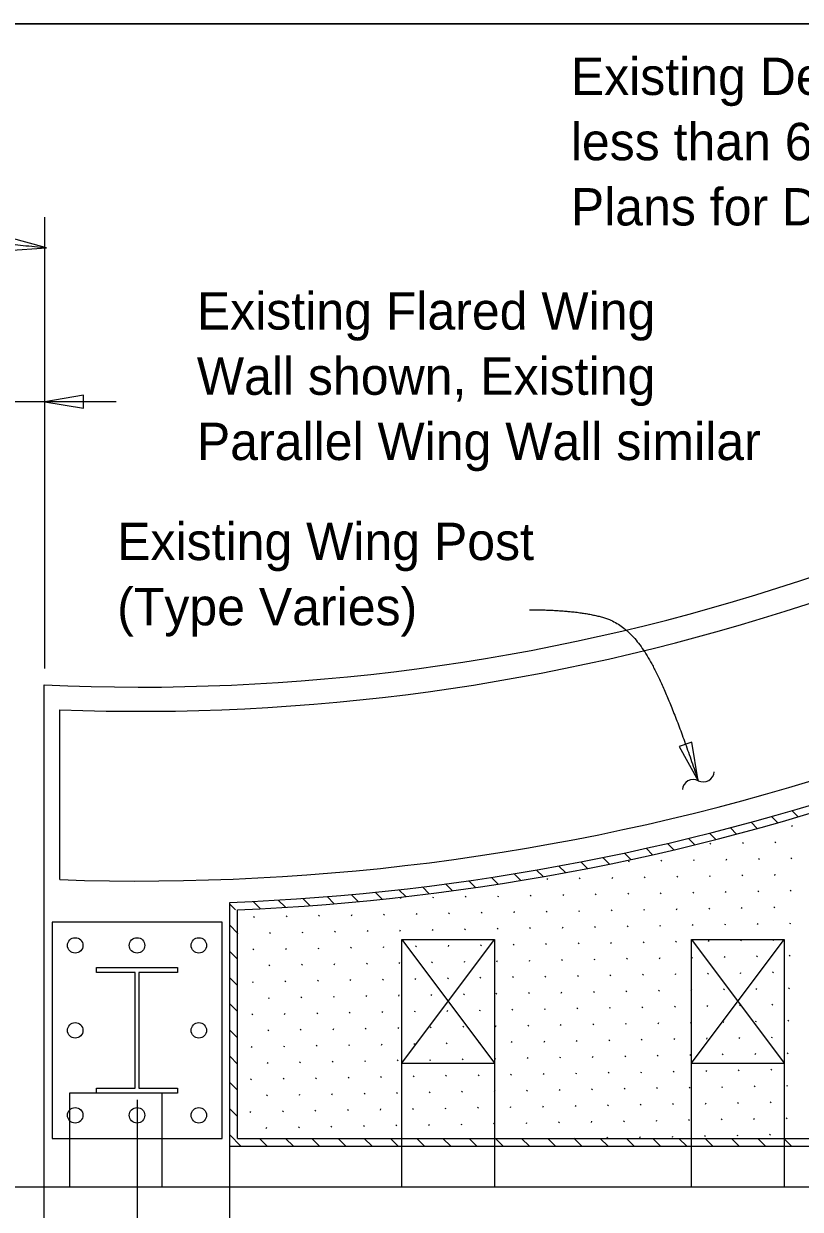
# Model space of a CAD drawing. Extents: x 0 to 41.1, y 0 to 25.9.
# Drawn here: x 27.57 to 31.76, y 19.55 to 25.95 of the extents above; entities that cross this region are included whole.
import ezdxf

# ---------------------------------------------------------------- set-up
doc = ezdxf.new("R2010")
doc.units = 0
for name, color, linetype in [('Dimension', 7, 'Continuous'), ('ExistSuperStruct', 7, 'Continuous'), ('Miscellaneous', 7, 'Continuous'), ('Miscellaneous1', 7, 'Continuous'), ('SteelMisc_h', 7, 'Continuous')]:
    doc.layers.add(name, color=color, linetype=linetype)

msp = doc.modelspace()

# ---------------------------------------------------------------- linework, layer by layer
at = {"layer": 'Dimension'}
for p, q in [((27.6878, 22.467), (27.6878, 24.9023)), ((28.0733, 23.9065), (23.9735, 23.9065)), ((28.1854, 20.1392), (28.1854, 17.6446))]:
    msp.add_line(p, q, dxfattribs=at)
for points in [[(0, 0), (41.0506, 0), (41.0506, 25.9461), (0, 25.9461)], [(27.6973, 24.7374), (27.4936, 24.7932), (27.4865, 24.723)], [(27.6879, 23.9065), (27.8961, 23.8712), (27.8961, 23.9418)], [(31.2113, 21.8616), (31.1762, 22.0699), (31.1095, 22.0467)]]:
    msp.add_lwpolyline(points, close=True, dxfattribs=at)
for centre, start, end in [((31.2387, 21.9152), 243.37602, 355.10324), ((31.1853, 21.8086), 63.37602, 175.10324)]:
    msp.add_arc(centre, 0.0596, start, end, dxfattribs=at)
for points in [[(26.5757, 24.9815), (26.7604, 24.9749), (26.9979, 24.8759), (27.0309, 24.8165), (27.3014, 24.7769), (27.6972, 24.7373)], [(30.3021, 22.7841), (30.5512, 22.7841), (30.8439, 22.7031), (31.0618, 22.3104), (31.2113, 21.8616)]]:
    msp.add_open_spline(points, degree=2, dxfattribs=at)
at = {"layer": 'ExistSuperStruct'}
for p, q in [((27.6854, 17.9125), (27.6854, 22.3785)), ((27.7687, 21.328), (27.7687, 22.244)), ((28.6854, 17.9125), (28.6854, 21.205)), ((28.7271, 19.9322), (28.7271, 21.165)), ((28.7271, 19.9322), (35.7954, 19.9322)), ((28.6854, 19.8905), (35.7954, 19.8905))]:
    msp.add_line(p, q, dxfattribs=at)
for radius, start, end in [(11.3394, 267.40102, 307.93264), (11.4702, 267.84731, 307.49092), (12.3856, 268.00648, 307.27295), (12.5106, 272.22541, 307.24718), (12.5523, 272.40859, 307.2387)]:
    msp.add_arc((28.1995, 33.7062), radius, start, end, dxfattribs=at)
at = {"layer": 'Miscellaneous'}
for p, q in [((31.7168, 21.7002), (31.7504, 21.6666)), ((31.4964, 21.6378), (31.5302, 21.6039)), ((31.607, 21.6685), (31.6403, 21.6352)), ((31.7163, 21.6156), (31.7195, 21.6212)), ((31.2725, 21.5788), (31.3067, 21.5446)), ((31.3848, 21.6078), (31.4185, 21.5742)), ((30.9299, 21.4971), (30.9643, 21.4627)), ((31.045, 21.5234), (31.0796, 21.4888)), ((31.1592, 21.5507), (31.1932, 21.5166)), ((31.2764, 21.5199), (31.2797, 21.5255)), ((31.4517, 21.5231), (31.455, 21.5287)), ((31.627, 21.5264), (31.6303, 21.532)), ((30.6968, 21.4473), (30.7317, 21.4125)), ((30.8138, 21.4717), (30.8488, 21.4368)), ((30.8365, 21.4241), (30.8398, 21.4297)), ((31.0118, 21.4274), (31.0151, 21.433)), ((31.1871, 21.4306), (31.1904, 21.4362)), ((31.3624, 21.4339), (31.3657, 21.4395)), ((31.5377, 21.4371), (31.541, 21.4427)), ((31.7131, 21.4403), (31.7163, 21.4459)), ((30.3399, 21.38), (30.3756, 21.3443)), ((30.4599, 21.4014), (30.4952, 21.3661)), ((30.5789, 21.4239), (30.6142, 21.3886)), ((29.8494, 21.3048), (29.886, 21.2682)), ((29.9737, 21.322), (30.0102, 21.2855)), ((30.0968, 21.3402), (30.133, 21.3041)), ((30.2189, 21.3596), (30.2548, 21.3237)), ((30.3967, 21.3284), (30.3999, 21.334)), ((30.572, 21.3316), (30.5752, 21.3372)), ((30.7473, 21.3349), (30.7505, 21.3405)), ((30.9226, 21.3381), (30.9258, 21.3437)), ((31.0979, 21.3413), (31.1011, 21.3469)), ((31.2732, 21.3446), (31.2764, 21.3502)), ((31.4485, 21.3478), (31.4517, 21.3534)), ((31.6238, 21.3511), (31.627, 21.3567)), ((29.3408, 21.2477), (29.3786, 21.2099)), ((29.4698, 21.2602), (29.5077, 21.2223)), ((29.5975, 21.2739), (29.6347, 21.2367)), ((29.724, 21.2888), (29.7612, 21.2516)), ((29.9568, 21.2326), (29.96, 21.2382)), ((30.1321, 21.2359), (30.1353, 21.2415)), ((30.3074, 21.2391), (30.3106, 21.2447)), ((30.4827, 21.2424), (30.4859, 21.2479)), ((30.658, 21.2456), (30.6612, 21.2512)), ((30.8333, 21.2488), (30.8365, 21.2544)), ((31.0086, 21.2521), (31.0118, 21.2577)), ((31.1839, 21.2553), (31.1871, 21.2609)), ((31.3592, 21.2586), (31.3624, 21.2642)), ((31.5345, 21.2618), (31.5377, 21.2674)), ((31.7098, 21.265), (31.7131, 21.2706)), ((28.6854, 21.1961), (28.7164, 21.165)), ((28.8123, 21.2106), (28.8518, 21.171)), ((28.9464, 21.2179), (28.9853, 21.1789)), ((29.0792, 21.2265), (29.1178, 21.1879)), ((29.2106, 21.2365), (29.249, 21.1981)), ((29.6062, 21.2261), (29.6094, 21.2317)), ((29.7815, 21.2294), (29.7847, 21.235)), ((31.2699, 21.1693), (31.2732, 21.1749)), ((31.4452, 21.1725), (31.4485, 21.1781)), ((31.6205, 21.1758), (31.6238, 21.1814)), ((28.8157, 21.1239), (28.8189, 21.1295)), ((28.991, 21.1272), (28.9942, 21.1327)), ((29.1663, 21.1304), (29.1695, 21.136)), ((29.3416, 21.1336), (29.3448, 21.1392)), ((29.5169, 21.1369), (29.5201, 21.1425)), ((29.6922, 21.1401), (29.6954, 21.1457)), ((29.8675, 21.1434), (29.8707, 21.149)), ((30.0428, 21.1466), (30.046, 21.1522)), ((30.2181, 21.1498), (30.2213, 21.1554)), ((30.3934, 21.1531), (30.3967, 21.1587)), ((30.5687, 21.1563), (30.572, 21.1619)), ((30.744, 21.1596), (30.7473, 21.1652)), ((30.9193, 21.1628), (30.9226, 21.1684)), ((31.0946, 21.166), (31.0979, 21.1716)), ((28.6854, 21.0818), (28.7271, 21.0401)), ((29.077, 21.0411), (29.0803, 21.0467)), ((29.2523, 21.0444), (29.2556, 21.05)), ((29.4276, 21.0476), (29.4309, 21.0532)), ((29.6029, 21.0508), (29.6062, 21.0564)), ((29.7782, 21.0541), (29.7815, 21.0597)), ((29.9535, 21.0573), (29.9568, 21.0629)), ((30.1288, 21.0606), (30.1321, 21.0662)), ((30.3041, 21.0638), (30.3074, 21.0694)), ((30.4794, 21.067), (30.4827, 21.0726)), ((30.6547, 21.0703), (30.658, 21.0759)), ((30.8301, 21.0735), (30.8333, 21.0791)), ((31.0054, 21.0768), (31.0086, 21.0824)), ((31.1807, 21.08), (31.1839, 21.0856)), ((31.356, 21.0833), (31.3592, 21.0889)), ((31.5313, 21.0865), (31.5345, 21.0921)), ((31.7066, 21.0897), (31.7098, 21.0953)), ((28.7271, 21.0358), (28.7296, 21.0402)), ((28.9017, 21.0379), (28.905, 21.0435)), ((29.6124, 19.6709), (29.6124, 21.0042)), ((29.6124, 21.0042), (30.1124, 21.0042)), ((29.6124, 21.0042), (30.1124, 20.3376)), ((29.6124, 20.3376), (30.1124, 21.0042)), ((30.1124, 21.0042), (30.1124, 19.6709)), ((30.3902, 20.9778), (30.3934, 20.9834)), ((30.5655, 20.981), (30.5687, 20.9866)), ((30.7408, 20.9843), (30.744, 20.9899)), ((30.9161, 20.9875), (30.9193, 20.9931)), ((31.0914, 20.9907), (31.0946, 20.9963)), ((31.1749, 19.6709), (31.1749, 21.0042)), ((31.1749, 21.0042), (31.6749, 21.0042)), ((31.1749, 21.0042), (31.6749, 20.3376)), ((31.1749, 20.3376), (31.6749, 21.0042)), ((31.2667, 20.994), (31.2699, 20.9996)), ((31.442, 20.9972), (31.4452, 21.0028)), ((31.6173, 21.0005), (31.6205, 21.0061)), ((31.6749, 21.0042), (31.6749, 19.6709)), ((28.6854, 20.9404), (28.7271, 20.8987)), ((28.8124, 20.9486), (28.8157, 20.9542)), ((28.9877, 20.9518), (28.991, 20.9574)), ((29.163, 20.9551), (29.1663, 20.9607)), ((29.3384, 20.9583), (29.3416, 20.9639)), ((29.5137, 20.9616), (29.5169, 20.9672)), ((29.689, 20.9648), (29.6922, 20.9704)), ((29.8643, 20.9681), (29.8675, 20.9737)), ((30.0396, 20.9713), (30.0428, 20.9769)), ((30.2149, 20.9745), (30.2181, 20.9801)), ((31.7033, 20.9144), (31.7066, 20.92)), ((28.8985, 20.8626), (28.9017, 20.8682)), ((29.0738, 20.8658), (29.077, 20.8714)), ((29.2491, 20.8691), (29.2523, 20.8747)), ((29.4244, 20.8723), (29.4276, 20.8779)), ((29.5997, 20.8755), (29.6029, 20.8811)), ((29.775, 20.8788), (29.7782, 20.8844)), ((29.9503, 20.882), (29.9535, 20.8876)), ((30.1256, 20.8853), (30.1288, 20.8909)), ((30.3009, 20.8885), (30.3041, 20.8941)), ((30.4762, 20.8917), (30.4794, 20.8973)), ((30.6515, 20.895), (30.6547, 20.9006)), ((30.8268, 20.8982), (30.8301, 20.9038)), ((31.0021, 20.9015), (31.0054, 20.9071)), ((31.1774, 20.9047), (31.1807, 20.9103)), ((31.3527, 20.9079), (31.356, 20.9135)), ((31.528, 20.9112), (31.5313, 20.9168)), ((28.6854, 20.799), (28.7271, 20.7573)), ((29.5104, 20.7863), (29.5137, 20.7919)), ((29.6857, 20.7895), (29.689, 20.7951)), ((29.861, 20.7927), (29.8643, 20.7983)), ((30.0363, 20.796), (30.0396, 20.8016)), ((30.2116, 20.7992), (30.2149, 20.8048)), ((30.3869, 20.8025), (30.3902, 20.8081)), ((30.5622, 20.8057), (30.5655, 20.8113)), ((30.7375, 20.809), (30.7408, 20.8146)), ((30.9128, 20.8122), (30.9161, 20.8178)), ((31.0881, 20.8154), (31.0914, 20.821)), ((31.2634, 20.8187), (31.2667, 20.8243)), ((31.4388, 20.8219), (31.442, 20.8275)), ((31.6141, 20.8252), (31.6173, 20.8308)), ((28.8092, 20.7733), (28.8124, 20.7789)), ((28.9845, 20.7765), (28.9877, 20.7821)), ((29.1598, 20.7798), (29.163, 20.7854)), ((29.3351, 20.783), (29.3384, 20.7886)), ((30.8236, 20.7229), (30.8268, 20.7285)), ((30.9989, 20.7262), (31.0021, 20.7318)), ((31.1742, 20.7294), (31.1774, 20.735)), ((31.3495, 20.7326), (31.3527, 20.7382)), ((31.5248, 20.7359), (31.528, 20.7415)), ((31.7001, 20.7391), (31.7033, 20.7447)), ((28.8952, 20.6873), (28.8985, 20.6929)), ((29.0705, 20.6905), (29.0738, 20.6961)), ((29.2458, 20.6938), (29.2491, 20.6994)), ((29.4211, 20.697), (29.4244, 20.7026)), ((29.5964, 20.7002), (29.5997, 20.7058)), ((29.7717, 20.7035), (29.775, 20.7091)), ((29.9471, 20.7067), (29.9503, 20.7123)), ((30.1224, 20.71), (30.1256, 20.7156)), ((30.2977, 20.7132), (30.3009, 20.7188)), ((30.473, 20.7164), (30.4762, 20.722)), ((30.6483, 20.7197), (30.6515, 20.7253)), ((28.6854, 20.6575), (28.7271, 20.6158)), ((28.806, 20.598), (28.8092, 20.6036)), ((28.9813, 20.6012), (28.9845, 20.6068)), ((29.1566, 20.6045), (29.1598, 20.6101)), ((29.3319, 20.6077), (29.3351, 20.6133)), ((29.5072, 20.611), (29.5104, 20.6166)), ((29.6825, 20.6142), (29.6857, 20.6198)), ((29.8578, 20.6174), (29.861, 20.623)), ((30.0331, 20.6207), (30.0363, 20.6263)), ((30.2084, 20.6239), (30.2116, 20.6295)), ((30.3837, 20.6272), (30.3869, 20.6328)), ((30.559, 20.6304), (30.5622, 20.636)), ((30.7343, 20.6337), (30.7375, 20.6392)), ((30.9096, 20.6369), (30.9128, 20.6425)), ((31.0849, 20.6401), (31.0881, 20.6457)), ((31.2602, 20.6434), (31.2634, 20.649)), ((31.4355, 20.6466), (31.4388, 20.6522)), ((31.6108, 20.6499), (31.6141, 20.6555)), ((29.7685, 20.5282), (29.7717, 20.5338)), ((29.9438, 20.5314), (29.9471, 20.537)), ((30.1191, 20.5347), (30.1224, 20.5403)), ((30.2944, 20.5379), (30.2977, 20.5435)), ((30.4697, 20.5411), (30.473, 20.5467)), ((30.645, 20.5444), (30.6483, 20.55)), ((30.8203, 20.5476), (30.8236, 20.5532)), ((30.9956, 20.5509), (30.9989, 20.5565)), ((31.1709, 20.5541), (31.1742, 20.5597)), ((31.3462, 20.5573), (31.3495, 20.5629)), ((31.5215, 20.5606), (31.5248, 20.5662)), ((31.6968, 20.5638), (31.7001, 20.5694)), ((28.6854, 20.5161), (28.7271, 20.4744)), ((28.892, 20.512), (28.8952, 20.5176)), ((29.0673, 20.5152), (29.0705, 20.5208)), ((29.2426, 20.5185), (29.2458, 20.524)), ((29.4179, 20.5217), (29.4211, 20.5273)), ((29.5932, 20.5249), (29.5964, 20.5305)), ((31.0817, 20.4648), (31.0849, 20.4704)), ((31.257, 20.4681), (31.2602, 20.4737)), ((31.4323, 20.4713), (31.4355, 20.4769)), ((31.6076, 20.4746), (31.6108, 20.4801)), ((28.8027, 20.4227), (28.806, 20.4283)), ((28.978, 20.4259), (28.9813, 20.4315)), ((29.1533, 20.4292), (29.1566, 20.4348)), ((29.3286, 20.4324), (29.3319, 20.438)), ((29.5039, 20.4357), (29.5072, 20.4413)), ((29.6792, 20.4389), (29.6825, 20.4445)), ((29.8545, 20.4421), (29.8578, 20.4477)), ((30.0298, 20.4454), (30.0331, 20.451)), ((30.2051, 20.4486), (30.2084, 20.4542)), ((30.3804, 20.4519), (30.3837, 20.4575)), ((30.5558, 20.4551), (30.559, 20.4607)), ((30.7311, 20.4583), (30.7343, 20.4639)), ((30.9064, 20.4616), (30.9096, 20.4672)), ((28.6854, 20.3747), (28.7271, 20.333)), ((28.8887, 20.3367), (28.892, 20.3423)), ((29.0641, 20.3399), (29.0673, 20.3455)), ((29.2394, 20.3431), (29.2426, 20.3487)), ((29.4147, 20.3464), (29.4179, 20.352)), ((29.59, 20.3496), (29.5932, 20.3552)), ((29.7653, 20.3529), (29.7685, 20.3585)), ((29.9406, 20.3561), (29.9438, 20.3617)), ((30.1159, 20.3594), (30.1191, 20.3649)), ((30.2912, 20.3626), (30.2944, 20.3682)), ((30.4665, 20.3658), (30.4697, 20.3714)), ((30.6418, 20.3691), (30.645, 20.3747)), ((30.8171, 20.3723), (30.8203, 20.3779)), ((30.9924, 20.3756), (30.9956, 20.3812)), ((31.1677, 20.3788), (31.1709, 20.3844)), ((31.343, 20.382), (31.3462, 20.3876)), ((31.5183, 20.3853), (31.5215, 20.3909)), ((31.6936, 20.3885), (31.6968, 20.3941)), ((29.6124, 20.3376), (30.1124, 20.3376)), ((30.2019, 20.2733), (30.2051, 20.2789)), ((30.3772, 20.2766), (30.3804, 20.2822)), ((30.5525, 20.2798), (30.5558, 20.2854)), ((30.7278, 20.283), (30.7311, 20.2886)), ((30.9031, 20.2863), (30.9064, 20.2919)), ((31.0784, 20.2895), (31.0817, 20.2951)), ((31.1749, 20.3376), (31.6749, 20.3376)), ((31.2537, 20.2928), (31.257, 20.2984)), ((31.429, 20.296), (31.4323, 20.3016)), ((31.6043, 20.2992), (31.6076, 20.3048)), ((28.6854, 20.2333), (28.7271, 20.1916)), ((28.7995, 20.2474), (28.8027, 20.253)), ((28.9748, 20.2506), (28.978, 20.2562)), ((29.1501, 20.2539), (29.1533, 20.2595)), ((29.3254, 20.2571), (29.3286, 20.2627)), ((29.5007, 20.2604), (29.5039, 20.266)), ((29.676, 20.2636), (29.6792, 20.2692)), ((29.8513, 20.2668), (29.8545, 20.2724)), ((30.0266, 20.2701), (30.0298, 20.2757)), ((31.5151, 20.21), (31.5183, 20.2156)), ((31.6904, 20.2132), (31.6936, 20.2188)), ((28.3208, 20.1764), (27.8208, 20.1764)), ((27.8208, 20.1764), (27.8208, 19.6709)), ((28.3208, 19.6709), (28.3208, 20.1764)), ((28.8855, 20.1614), (28.8887, 20.167)), ((29.0608, 20.1646), (29.0641, 20.1702)), ((29.2361, 20.1678), (29.2394, 20.1734)), ((29.4114, 20.1711), (29.4147, 20.1767)), ((29.5867, 20.1743), (29.59, 20.1799)), ((29.762, 20.1776), (29.7653, 20.1832)), ((29.9373, 20.1808), (29.9406, 20.1864)), ((30.1126, 20.184), (30.1159, 20.1896)), ((30.2879, 20.1873), (30.2912, 20.1929)), ((30.4632, 20.1905), (30.4665, 20.1961)), ((30.6385, 20.1938), (30.6418, 20.1994)), ((30.8138, 20.197), (30.8171, 20.2026)), ((30.9891, 20.2003), (30.9924, 20.2059)), ((31.1645, 20.2035), (31.1677, 20.2091)), ((31.3398, 20.2067), (31.343, 20.2123)), ((28.6854, 20.0919), (28.7271, 20.0502)), ((29.3221, 20.0818), (29.3254, 20.0874)), ((29.4974, 20.0851), (29.5007, 20.0907)), ((29.6728, 20.0883), (29.676, 20.0939)), ((29.8481, 20.0915), (29.8513, 20.0971)), ((30.0234, 20.0948), (30.0266, 20.1004)), ((30.1987, 20.098), (30.2019, 20.1036)), ((30.374, 20.1013), (30.3772, 20.1069)), ((30.5493, 20.1045), (30.5525, 20.1101)), ((30.7246, 20.1077), (30.7278, 20.1133)), ((30.8999, 20.111), (30.9031, 20.1166)), ((31.0752, 20.1142), (31.0784, 20.1198)), ((31.2505, 20.1175), (31.2537, 20.1231)), ((31.4258, 20.1207), (31.429, 20.1263)), ((31.6011, 20.1239), (31.6043, 20.1295)), ((28.7962, 20.0721), (28.7995, 20.0777)), ((28.9715, 20.0753), (28.9748, 20.0809)), ((29.1468, 20.0786), (29.1501, 20.0842)), ((30.6353, 20.0185), (30.6385, 20.0241)), ((30.8106, 20.0217), (30.8138, 20.0273)), ((30.9859, 20.0249), (30.9891, 20.0305)), ((31.1612, 20.0282), (31.1645, 20.0338)), ((31.3365, 20.0314), (31.3398, 20.037)), ((31.5118, 20.0347), (31.5151, 20.0403)), ((31.6871, 20.0379), (31.6904, 20.0435)), ((28.8823, 19.9861), (28.8855, 19.9917)), ((29.0576, 19.9893), (29.0608, 19.9949)), ((29.2329, 19.9925), (29.2361, 19.9981)), ((29.4082, 19.9958), (29.4114, 20.0014)), ((29.5835, 19.999), (29.5867, 20.0046)), ((29.7588, 20.0023), (29.762, 20.0079)), ((29.9341, 20.0055), (29.9373, 20.0111)), ((30.1094, 20.0087), (30.1126, 20.0143)), ((30.2847, 20.012), (30.2879, 20.0176)), ((30.46, 20.0152), (30.4632, 20.0208)), ((28.6854, 19.9504), (28.7453, 19.8905)), ((28.845, 19.9322), (28.8867, 19.8905)), ((28.9865, 19.9322), (29.0282, 19.8905)), ((29.1279, 19.9322), (29.1696, 19.8905)), ((29.2693, 19.9322), (29.311, 19.8905)), ((29.4107, 19.9322), (29.4524, 19.8905)), ((29.5521, 19.9322), (29.5938, 19.8905)), ((29.6936, 19.9322), (29.7353, 19.8905)), ((29.835, 19.9322), (29.8767, 19.8905)), ((29.9764, 19.9322), (30.0181, 19.8905)), ((30.1178, 19.9322), (30.1595, 19.8905)), ((30.2593, 19.9322), (30.301, 19.8905)), ((30.4007, 19.9322), (30.4424, 19.8905)), ((30.5421, 19.9322), (30.5838, 19.8905)), ((30.5477, 19.9322), (30.5493, 19.9348)), ((30.6835, 19.9322), (30.7252, 19.8905)), ((30.7213, 19.9324), (30.7246, 19.938)), ((30.8249, 19.9322), (30.8666, 19.8905)), ((30.8966, 19.9357), (30.8999, 19.9413)), ((30.9664, 19.9322), (31.0081, 19.8905)), ((31.0719, 19.9389), (31.0752, 19.9445)), ((31.1078, 19.9322), (31.1495, 19.8905)), ((31.2472, 19.9422), (31.2505, 19.9478)), ((31.2492, 19.9322), (31.2909, 19.8905)), ((31.3906, 19.9322), (31.4323, 19.8905)), ((31.4225, 19.9454), (31.4258, 19.951)), ((31.532, 19.9322), (31.5737, 19.8905)), ((31.5979, 19.9486), (31.6011, 19.9542)), ((31.6735, 19.9322), (31.7152, 19.8905)), ((26.2319, 19.6709), (39.7792, 19.6709))]:
    msp.add_line(p, q, dxfattribs=at)
at = {"layer": 'Miscellaneous1'}
msp.add_lwpolyline([(0, 25.9461), (41.0506, 25.9461), (41.0506, 0), (0, 0)], close=True, dxfattribs=at)
at = {"layer": 'SteelMisc_h'}
msp.add_lwpolyline([(27.727, 19.9316), (28.6437, 19.9316), (28.6437, 21.0982), (27.727, 21.0982)], close=True, dxfattribs=at)
msp.add_lwpolyline([(28.4041, 20.1764), (27.9666, 20.1764), (27.9666, 20.2024), (28.1749, 20.2024), (28.1749, 20.8274), (27.9666, 20.8274), (27.9666, 20.8535), (28.4041, 20.8535), (28.4041, 20.8274), (28.1958, 20.8274), (28.1958, 20.2024), (28.4041, 20.2024), (28.4041, 20.1764)], dxfattribs=at)
for centre in [(27.852, 20.9732), (28.1854, 20.9732), (28.5187, 20.9732), (27.852, 20.5149), (28.5187, 20.5149), (27.852, 20.0566), (28.1854, 20.0566), (28.5187, 20.0566)]:
    msp.add_circle(centre, 0.0417, dxfattribs=at)

# ---------------------------------------------------------------- texts
at = {"layer": 'Dimension'}
for s, p in [('Existing Detached Sidewalk or Integral Sidewalk ', (30.5244, 25.5616)), ('less than 6" thick to be removed.  See Roadway ', (30.5244, 25.2096)), ('Plans for Details of Sidewalk replacement.', (30.5244, 24.8576)), ('Existing Flared Wing ', (28.508, 24.2959)), ('Wall shown, Existing ', (28.508, 23.9439)), ('Parallel Wing Wall similar', (28.508, 23.5919)), ('Existing Wing Post ', (28.0783, 23.0522)), ('(Type Varies)', (28.0783, 22.7002))]:
    msp.add_text(s, height=0.2016, dxfattribs=at).set_placement(p)

doc.saveas('drawing.dxf')
